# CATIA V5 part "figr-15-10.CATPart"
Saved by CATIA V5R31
Part number: Part1
Bounding box of the stored display mesh (mm): x -50 to 50, y -32.5 to 33.5, z -52 to 1
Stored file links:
  D:\PROJECTS\Project 2021\US EDITION\CATIA V5 6R 2021\Resources\Part Files\c15_catia_v5_6r2021_prt\figr-15-10.CATPart
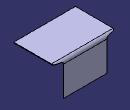
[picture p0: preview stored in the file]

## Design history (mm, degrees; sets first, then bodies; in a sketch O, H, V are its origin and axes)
SheetMetalParameters1: Thickness 1, BendRadius 4, KFactor 0.475772 {= log(min(100,max(20*SheetMetalParameters1.BendRadius,SheetMetalParameters1.Thickness)/SheetMetalParameters1.Thickness))/log(100)/2}, ReliefRadialLength 4, ReliefAxialLength 4, MinimumBendRadius 0
Body1 (main body)
  Sketch1 on xy-plane, origin (0, 0, 0), H (1, 0, 0), V (0, 1, 0)
    line L1 (-50, 32.5) -> (50, 32.5)
    line L2 (50, 32.5) -> (50, -32.5)
    line L3 (50, -32.5) -> (-50, -32.5)
    line L4 (-50, -32.5) -> (-50, 32.5)
    length L1 = 100
    length L2 = 65
    horizontal: L1 H, L3 H
    vertical: L2 V, L4 V
    symmetry: L4 L2 V, L1 L3 H
  Wall1: Thickness 1, Profile Sketch1
  d_NewWallOnEdge1: NewWallOnEdge_Edge edge [face of Wall1 | face of Wall1], NewWallOnEdge_Length 53, NewWallOnEdge_HeightLimitOffset 0, NewWallOnEdge_WidthOffset1 -15, NewWallOnEdge_WidthOffset2 -15, NewWallOnEdge_Angle 90, NewWallOnEdge_BendRadiusValue 4 {= SheetMetalParameters1.BendRadius}, NewWallOnEdge_BendTable SheetMetalParameters1, KFacteur 0.475772 {= log(min(100,max(20*d_NewWallOnEdge1.Radius,SheetMetalParameters1.Thickness)/SheetMetalParameters1.Thickness))/log(100)/2}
